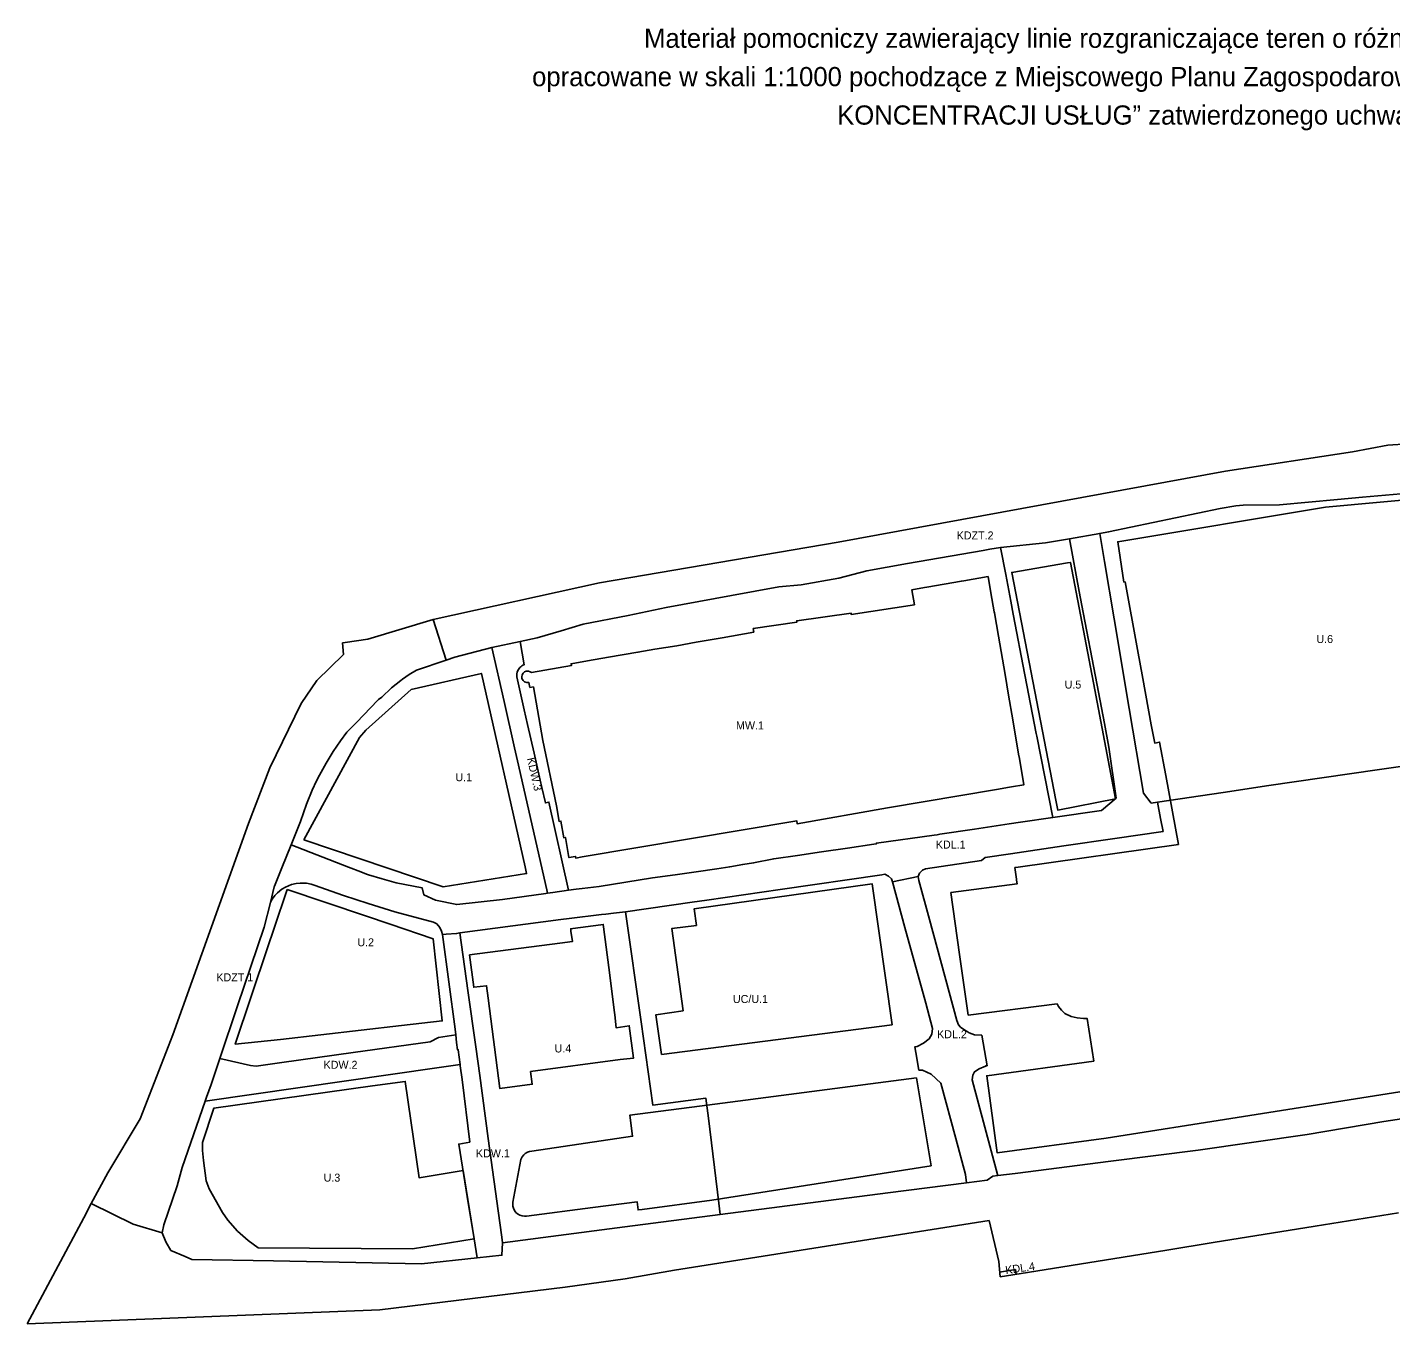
# Model space of a CAD drawing. Extents: x 7426373 to 7428079, y 5550400 to 5551210.
# Drawn here: x 7426373 to 7427225, y 5550400 to 5551210 of the extents above; entities that cross this region are included whole.
import ezdxf

# ---------------------------------------------------------------- set-up
doc = ezdxf.new("R2010")
doc.units = 0
for name, color, linetype in [('info', 7, 'Continuous'), ('linie rozgraniczające', 7, 'Continuous'), ('nieprzekraczalne linie zabudowy', 7, 'Continuous'), ('obowiazujace linie zabudowy', 7, 'Continuous'), ('przeznaczenia terenów', 7, 'Continuous')]:
    doc.layers.add(name, color=color, linetype=linetype)

msp = doc.modelspace()

# ---------------------------------------------------------------- linework, layer by layer
at = {"layer": 'linie rozgraniczające'}
for p, q in [((7427200.83, 5550944.38), (7427121.57, 5550932.18)), ((7427121.57, 5550932.18), (7426879.43, 5550887.96)), ((7426879.43, 5550887.96), (7426730.45, 5550862.43)), ((7426730.45, 5550862.43), (7426626.47, 5550839.54)), ((7426626.47, 5550839.54), (7426634.6, 5550814.16)), ((7426571.44, 5550825.22), (7426569.8, 5550824.98)), ((7426569.8, 5550824.98), (7426570.42, 5550817.78)), ((7426544.01, 5550787.1), (7426524.3, 5550746.79)), ((7426913.49, 5550675.69), (7426929.4, 5550678.9)), ((7426408.16, 5550465.79), (7426372.85, 5550399.52)), ((7426777.24, 5550432.91), (7426973.92, 5550463.96)), ((7426973.92, 5550463.96), (7426979.89, 5550438.33)), ((7426979.89, 5550438.33), (7426980.6, 5550428.75)), ((7426746.5, 5550427.54), (7426777.24, 5550432.91)), ((7426990.26, 5550433.4), (7426980.37, 5550431.84)), ((7426990.59, 5550430.37), (7426990.26, 5550433.4))]:
    msp.add_line(p, q, dxfattribs=at)
for points in [[(7427299.9, 5550956.76), (7427299.03, 5550953.57), (7427222.94, 5550948.43), (7427200.83, 5550944.38)], [(7427231.06, 5550918.04), (7427207, 5550916.03), (7427191.46, 5550914.56), (7427155.25, 5550911.14), (7427132.43, 5550911.02), (7427128, 5550910.66), (7427118.17, 5550908.95), (7427048.39, 5550894.28), (7427042.86, 5550893.33), (7427023.95, 5550890.06), (7427008.92, 5550887.47), (7426980.93, 5550884.56), (7426974.25, 5550883.46), (7426970.17, 5550882.71), (7426922.78, 5550874.54), (7426897.33, 5550869.9), (7426879.87, 5550865.38), (7426856.3, 5550861.2), (7426842.51, 5550859.92), (7426812.77, 5550854.5), (7426772.12, 5550847.06), (7426748.24, 5550842.12), (7426720.26, 5550836.75), (7426706.41, 5550832.57), (7426691.43, 5550828.11)], [(7427043.94, 5550720.28), (7427053.16, 5550727.95), (7427048.64, 5550759.91), (7427045.81, 5550774.61), (7427040.16, 5550804.03), (7427032.61, 5550844), (7427030.14, 5550857.04), (7427023.95, 5550890.06)], [(7427074.95, 5550724.79), (7427070.3, 5550731.05), (7427061.21, 5550783.95), (7427051.87, 5550839.95), (7427045.87, 5550875.92), (7427042.86, 5550893.33)], [(7426980.93, 5550884.56), (7426984.14, 5550867.7), (7426987.35, 5550851.06), (7426988.81, 5550842.84), (7426991.04, 5550831.04), (7426993.72, 5550816.94), (7427003.23, 5550768.45), (7427003.57, 5550766.7), (7427013.55, 5550715.81)], [(7426626.47, 5550839.54), (7426585.7, 5550827.19), (7426571.44, 5550825.22)], [(7426524.72, 5550662.81), (7426527.19, 5550672.58), (7426527.36, 5550673), (7426531.93, 5550684.33), (7426537.7, 5550698.68), (7426543.64, 5550713.44), (7426547.28, 5550724.24), (7426550.84, 5550733.01), (7426553.65, 5550738.79), (7426555.39, 5550742.41), (7426559.69, 5550749.76), (7426563.99, 5550757.12), (7426568.62, 5550763.72), (7426572.53, 5550769.08), (7426578.54, 5550775.3), (7426591.9, 5550789.09), (7426592.39, 5550789.67), (7426594.4, 5550791.12), (7426600.45, 5550796.8), (7426603.39, 5550799.16), (7426606.33, 5550801.51), (7426607.38, 5550802.27), (7426611.43, 5550805.25), (7426615.97, 5550807.98), (7426634.6, 5550814.16), (7426640, 5550815.95), (7426663.15, 5550822.11), (7426680.85, 5550825.86), (7426691.43, 5550828.11)], [(7426663.15, 5550822.11), (7426670.78, 5550788.36), (7426677.33, 5550759.36), (7426679.17, 5550751.18), (7426697.37, 5550670.68), (7426697.85, 5550668.55)], [(7426680.85, 5550825.86), (7426683.34, 5550811.31), (7426682.55, 5550810.97), (7426681.9, 5550810.58), (7426681.2, 5550810.05), (7426680.62, 5550809.49), (7426680.15, 5550808.92), (7426679.41, 5550807.72), (7426678.99, 5550806.65), (7426678.74, 5550805.54), (7426678.67, 5550804.29), (7426678.74, 5550803.66), (7426683.4, 5550783.18), (7426685.48, 5550773.89), (7426689.5, 5550756.06), (7426690.79, 5550750.53), (7426692.91, 5550740.96), (7426693.3, 5550739.23), (7426694.28, 5550734.61), (7426696.53, 5550724.93), (7426698.72, 5550725.49), (7426711.08, 5550670.36)], [(7426570.42, 5550817.78), (7426553.66, 5550801.56), (7426544.01, 5550787.1)], [(7427281.67, 5550755.01), (7427216.25, 5550745.55), (7427148.47, 5550735.75), (7427120.11, 5550731.52), (7427078.99, 5550725.38), (7427074.95, 5550724.79)], [(7426524.3, 5550746.79), (7426511.17, 5550712.2), (7426463.78, 5550579.96)], [(7427078.99, 5550725.38), (7427080.96, 5550715.19), (7427082.53, 5550707.01)], [(7427043.94, 5550720.28), (7427013.55, 5550715.81), (7426993.42, 5550712.93), (7426986.37, 5550711.87), (7426964.74, 5550708.62), (7426943.1, 5550705.38), (7426941.25, 5550705.12), (7426939.4, 5550704.86), (7426903.41, 5550699.82), (7426903.51, 5550699.49), (7426901.68, 5550699.23), (7426885.36, 5550696.76), (7426869.03, 5550694.3), (7426854.16, 5550692.2), (7426839.28, 5550690.09), (7426826.6, 5550687.52), (7426819.84, 5550686.5), (7426811.75, 5550685.11), (7426803.66, 5550683.71), (7426790.69, 5550681.84), (7426777.72, 5550679.97), (7426763.45, 5550678.23), (7426730.17, 5550672.78), (7426719.53, 5550671.43), (7426715.8, 5550670.99), (7426711.08, 5550670.36), (7426701.12, 5550669.03), (7426697.85, 5550668.55), (7426696.81, 5550668.4), (7426669.74, 5550664.65), (7426641.2, 5550661.4), (7426627.88, 5550664.24), (7426620.57, 5550667.61), (7426619.64, 5550671.82), (7426603.32, 5550675), (7426594.65, 5550677.53), (7426585.97, 5550680.05), (7426584.78, 5550680.51), (7426581.25, 5550681.89), (7426573.65, 5550684.85), (7426537.7, 5550698.68)], [(7427082.53, 5550707.01), (7427052.26, 5550702.77), (7427020.37, 5550698.12), (7426987.13, 5550693.16), (7426971.27, 5550690.94), (7426969.02, 5550688.97), (7426934.05, 5550683.87), (7426932.12, 5550683.05), (7426930.2, 5550681.05), (7426929.4, 5550678.9), (7426929.93, 5550676.45), (7426936.44, 5550652.18), (7426953.6, 5550588.92), (7426954.62, 5550586.38), (7426955.96, 5550584.85), (7426958.58, 5550582.95), (7426960.08, 5550582.09), (7426961.4, 5550581.35), (7426964.66, 5550579.98), (7426969.15, 5550579.78), (7426972.52, 5550560.71), (7426971.43, 5550560.58), (7426971.46, 5550560.4), (7426967.5, 5550558.84), (7426964.65, 5550556.93), (7426963.52, 5550554.77), (7426963.28, 5550551.9), (7426979.05, 5550492.76), (7426979.22, 5550492.13)], [(7426570.38, 5550667.05), (7426552.01, 5550673.64), (7426550.21, 5550674.16), (7426547.24, 5550674.73), (7426546.41, 5550674.84), (7426544.92, 5550674.91), (7426543.43, 5550674.91), (7426540.9, 5550674.69), (7426537.86, 5550673.94), (7426534.16, 5550672.34), (7426531.8, 5550671), (7426529.21, 5550668.88), (7426527.52, 5550667.11), (7426525.77, 5550664.78), (7426524.72, 5550662.81)], [(7426959.64, 5550487.59), (7426959.07, 5550492.74), (7426953.02, 5550515.22), (7426943.72, 5550549.78), (7426937.52, 5550555.5), (7426932.11, 5550558), (7426929.96, 5550558.02), (7426928.05, 5550568.96), (7426927.46, 5550572.57), (7426928.81, 5550572.74), (7426932.87, 5550574.92), (7426936.27, 5550577.63), (7426937.91, 5550580.54), (7426938.39, 5550584.1), (7426934.3, 5550599.93), (7426921.05, 5550647.07), (7426913.49, 5550675.69), (7426912.78, 5550677.58), (7426910.99, 5550679.29), (7426908.69, 5550680.35), (7426906.69, 5550680.05), (7426843.33, 5550670.89), (7426797.43, 5550664.26), (7426788.2, 5550662.92), (7426746.58, 5550656.9), (7426739.16, 5550656.05), (7426734.36, 5550655.47), (7426731.7, 5550655.17), (7426711.51, 5550652.67), (7426706.29, 5550652.03), (7426654.05, 5550645.24), (7426643.2, 5550643.74), (7426641.05, 5550643.37), (7426634.48, 5550642.9), (7426632.36, 5550642.72), (7426631.71, 5550644.74), (7426630.6, 5550647.15), (7426628.75, 5550649.41), (7426626.68, 5550650.52), (7426602.56, 5550656.94), (7426585.82, 5550662.05), (7426570.38, 5550667.05)], [(7426484.91, 5550541.11), (7426487.67, 5550549.1), (7426493.12, 5550565.25), (7426504.24, 5550598.2), (7426520.81, 5550647.3), (7426524.72, 5550662.81)], [(7426746.58, 5550656.9), (7426756.3, 5550588.21), (7426763.64, 5550536.2), (7426796.7, 5550540.55), (7426798.47, 5550527.9), (7426804.92, 5550474.95), (7426805.8, 5550467.73)], [(7426632.36, 5550642.72), (7426640.23, 5550583.58), (7426640.6, 5550580.07), (7426641.09, 5550575.27), (7426641.57, 5550570.68), (7426642.14, 5550570.77), (7426643.31, 5550561.53), (7426643.41, 5550560.74), (7426644.5, 5550552.12), (7426649.44, 5550512.93)], [(7426669.77, 5550450.17), (7426669.3, 5550453.64), (7426668.09, 5550462.55), (7426660.9, 5550515.36), (7426655.56, 5550554.61), (7426653.07, 5550572.53), (7426648.18, 5550607.78), (7426643.2, 5550643.74)], [(7426463.78, 5550579.96), (7426443.36, 5550527.61), (7426423.09, 5550493.8)], [(7426640.6, 5550580.07), (7426629.76, 5550578.4), (7426624.47, 5550575.59), (7426576.42, 5550568.92), (7426531.86, 5550562.73), (7426515.91, 5550560.51), (7426512.41, 5550560.84), (7426493.12, 5550565.25)], [(7426643.31, 5550561.53), (7426630.27, 5550559.66), (7426484.06, 5550538.65)], [(7426462.57, 5550445.22), (7426459.41, 5550450.72), (7426457.17, 5550456.35), (7426458.12, 5550461.3), (7426466.43, 5550485.7), (7426469.73, 5550497.17), (7426484.06, 5550538.65), (7426484.91, 5550541.11)], [(7426669.77, 5550450.17), (7426699.86, 5550454.06), (7426746.19, 5550460.04), (7426805.8, 5550467.73), (7426910.55, 5550481.26), (7426959.64, 5550487.59), (7426966.2, 5550488.44), (7426972.53, 5550489.26), (7426976.08, 5550491.73), (7426979.22, 5550492.13), (7426990.13, 5550493.5), (7427049.79, 5550501.06), (7427104.38, 5550507.97), (7427172.42, 5550517.71), (7427220.33, 5550525.84), (7427254.95, 5550531.02)], [(7426649.44, 5550512.93), (7426642.42, 5550511.79), (7426648.6, 5550473.89), (7426652.07, 5550452.58), (7426652.73, 5550448.53), (7426654, 5550440.74)], [(7426423.09, 5550493.8), (7426412.87, 5550474.63), (7426408.16, 5550465.79)], [(7426457.17, 5550456.35), (7426439.06, 5550461.64), (7426412.87, 5550474.63)], [(7426980.6, 5550428.75), (7426984.66, 5550429.41), (7426997.74, 5550431.53), (7427084.76, 5550445.54), (7427113.69, 5550450.21), (7427177.53, 5550460.5), (7427229.52, 5550468.88)], [(7426462.57, 5550445.22), (7426471.47, 5550441.49), (7426475.58, 5550439.76), (7426526.67, 5550438.74), (7426619.15, 5550436.96), (7426654, 5550440.74), (7426669.39, 5550442.28), (7426669.77, 5550450.17)], [(7426372.85, 5550399.52), (7426482.98, 5550403.88), (7426593.12, 5550408.24), (7426651.03, 5550415.3), (7426708.95, 5550422.37), (7426746.5, 5550427.54)]]:
    msp.add_lwpolyline(points, dxfattribs=at)
at = {"layer": 'nieprzekraczalne linie zabudowy'}
for p, q in [((7426694.94, 5550764.02), (7426694.94, 5550764.02)), ((7426530.97, 5550577.15), (7426606.59, 5550585.87))]:
    msp.add_line(p, q, dxfattribs=at)
for points in [[(7427408.31, 5550895.03), (7427406.05, 5550895.78), (7427347.6, 5550914.84), (7427315.95, 5550921.81), (7427184.04, 5550909.87), (7427054.18, 5550888.2), (7427058.04, 5550862.98), (7427058.77, 5550863.09), (7427066.5, 5550820.89)], [(7426987.97, 5550868.97), (7426987.97, 5550868.97), (7427015.49, 5550726.69), (7427016.7, 5550720.54), (7427052.76, 5550727.61), (7427039.91, 5550795.68), (7427024.56, 5550875.24), (7427022.74, 5550874.93), (7426987.97, 5550868.97)], [(7426927.21, 5550848.81), (7426887.65, 5550842.69), (7426887.61, 5550843.46), (7426853.56, 5550838.75), (7426853.69, 5550837.92), (7426826.46, 5550833.95), (7426826.86, 5550831.58)], [(7426683.89, 5550684.97), (7426656.55, 5550805.94), (7426612.68, 5550795.74), (7426584.31, 5550770.39), (7426580.37, 5550765.79), (7426545.71, 5550701.93)], [(7426694.94, 5550764.02), (7426703.47, 5550723.24), (7426705.09, 5550713.44), (7426706.24, 5550713.64), (7426708.03, 5550703.23), (7426709.08, 5550703.41), (7426711.25, 5550690.78), (7426715.39, 5550691.49), (7426715.55, 5550690.53), (7426719.6, 5550691.23)], [(7427084.17, 5550742.1), (7427092.19, 5550698.96)], [(7426719.6, 5550691.23), (7426853.7, 5550713.68), (7426853.84, 5550711.91), (7426910.3, 5550721.97), (7426978.42, 5550733.32)], [(7426545.71, 5550701.93), (7426632.77, 5550672.51), (7426684.82, 5550680.83), (7426683.89, 5550684.97)], [(7427092.19, 5550698.96), (7426992.04, 5550684.88), (7426989.87, 5550684.57)], [(7426989.87, 5550684.57), (7426990.86, 5550677.31), (7426990.87, 5550676.7), (7426991.27, 5550674.33), (7426949.91, 5550668.98), (7426955.34, 5550630.15), (7426957.17, 5550617.07), (7426960.63, 5550592.33)], [(7427046.83, 5550515.5), (7427456.13, 5550580.05), (7427468.63, 5550624.1)], [(7426960.63, 5550592.33), (7427016.25, 5550599.49)], [(7427016.25, 5550599.49), (7427017.05, 5550597.81), (7427018.92, 5550595.38), (7427021.11, 5550593.35), (7427024.97, 5550591.54), (7427028.9, 5550590.68), (7427032.73, 5550590.2), (7427034.96, 5550590.32), (7427039.19, 5550563.67)], [(7427039.19, 5550563.67), (7426972.3, 5550554.51), (7426978.92, 5550506.25), (7427046.83, 5550515.5)], [(7426517.15, 5550446.9), (7426613.55, 5550446.31), (7426652.07, 5550452.58), (7426645.12, 5550495.22), (7426617.67, 5550490.74), (7426608.97, 5550550.97), (7426588.44, 5550548.09), (7426489.35, 5550534.19), (7426482.29, 5550512.71)], [(7426800.47, 5550476.65), (7426937.48, 5550498.26), (7426928.41, 5550553.09)]]:
    msp.add_lwpolyline(points, dxfattribs=at)
at = {"layer": 'obowiazujace linie zabudowy'}
for p, q in [((7427084.17, 5550742.09), (7427084.17, 5550742.09)), ((7426769.1, 5550567.67), (7426913.22, 5550586.23))]:
    msp.add_line(p, q, dxfattribs=at)
for points in [[(7426978.42, 5550733.32), (7426986.52, 5550734.72), (7426987.67, 5550734.92), (7426995.55, 5550736.28), (7426992.49, 5550754.06), (7426992.37, 5550754.17), (7426988.61, 5550776.98), (7426985.99, 5550792.24), (7426983.76, 5550805.11), (7426979.62, 5550829.07), (7426977.08, 5550843.77), (7426976.98, 5550844.34), (7426974.91, 5550856.31), (7426973.16, 5550866.42), (7426958, 5550863.8), (7426956.52, 5550863.55), (7426934.97, 5550859.83), (7426933.45, 5550859.57), (7426925.58, 5550858.22), (7426927.21, 5550848.81)], [(7426826.86, 5550831.58), (7426806.94, 5550828.15), (7426790.79, 5550825.37), (7426778.6, 5550823.18), (7426764.96, 5550820.99), (7426754.4, 5550819.12), (7426736.08, 5550815.98), (7426722.95, 5550813.71), (7426712.62, 5550811.92), (7426712.82, 5550810.77), (7426687.82, 5550806.44), (7426687.03, 5550806.87), (7426686.09, 5550807.28), (7426685.59, 5550807.37), (7426684.49, 5550807.25), (7426683.5, 5550806.89), (7426682.59, 5550806.06), (7426682.1, 5550805.06), (7426681.76, 5550803.81), (7426681.92, 5550802.66), (7426682.6, 5550801.42), (7426683.54, 5550800.57), (7426684.97, 5550800.2), (7426686.26, 5550800.12), (7426686.84, 5550797.17), (7426689.04, 5550797.43), (7426694.94, 5550764.02)], [(7427066.5, 5550820.89), (7427069.81, 5550802.73), (7427075.13, 5550773.73), (7427077.24, 5550762.35), (7427080.3, 5550762.95), (7427084.17, 5550742.12)], [(7426913.22, 5550586.23), (7426900.66, 5550674.42), (7426789.53, 5550658.81), (7426790.96, 5550648.4)], [(7426535.27, 5550670.86), (7426527.12, 5550646.62), (7426523.04, 5550634.47), (7426502.76, 5550574.13), (7426530.97, 5550577.15)], [(7426606.59, 5550585.87), (7426632.13, 5550588.74), (7426626.36, 5550640.08), (7426599.5, 5550649.15), (7426584.18, 5550654.33), (7426535.27, 5550670.86)], [(7426790.96, 5550648.4), (7426775.46, 5550646.4), (7426782.74, 5550594.99)], [(7426782.74, 5550594.97), (7426765.6, 5550592.56), (7426769.1, 5550567.67)], [(7426928.41, 5550553.09), (7426792.9, 5550535.56), (7426749.39, 5550529.93), (7426751.08, 5550516.72), (7426688.18, 5550507.36), (7426686.66, 5550507.13), (7426685.31, 5550506.65), (7426683.99, 5550505.86), (7426683.03, 5550505.01), (7426682.05, 5550503.73), (7426681.27, 5550502.22), (7426676.24, 5550475.42), (7426676.24, 5550472.98), (7426676.54, 5550471.78), (7426677.22, 5550470.33), (7426678.12, 5550469.12), (7426679.2, 5550468.16), (7426680.5, 5550467.4), (7426681.98, 5550466.89), (7426683.41, 5550466.71), (7426684.76, 5550466.79), (7426726.21, 5550472.15), (7426753.84, 5550475.72), (7426754.49, 5550470.64), (7426756.96, 5550470.96), (7426800.47, 5550476.65)], [(7426482.29, 5550512.71), (7426482.4, 5550507.8), (7426482.99, 5550501.58), (7426484.69, 5550488.77), (7426486.46, 5550483.8)], [(7426486.46, 5550483.8), (7426494.92, 5550468.97), (7426498.23, 5550464.16), (7426504.2, 5550457.45), (7426510.84, 5550451.5), (7426517.15, 5550446.9)]]:
    msp.add_lwpolyline(points, dxfattribs=at)
msp.add_lwpolyline([(7426649.11, 5550630.05), (7426649.11, 5550630.04), (7426651.75, 5550609.74), (7426659.78, 5550610.77), (7426660.79, 5550602.94), (7426668.04, 5550546.52), (7426688.35, 5550549.14), (7426687.32, 5550557.13), (7426687.32, 5550557.13), (7426743.34, 5550564.56), (7426751.58, 5550565.41), (7426748.97, 5550585.74), (7426740.76, 5550584.48), (7426739.98, 5550592.54), (7426739.79, 5550593.98), (7426736.13, 5550622.11), (7426732.85, 5550647.54), (7426732.66, 5550649), (7426731.2, 5550648.81), (7426713.8, 5550646.55), (7426712.36, 5550646.36), (7426712.55, 5550644.92), (7426713.4, 5550638.36), (7426705.56, 5550637.37), (7426705.53, 5550637.37)], close=True, dxfattribs=at)

# ---------------------------------------------------------------- texts
at = {"layer": 'info'}
for s, p in [('Materiał pomocniczy zawierający linie rozgraniczające teren o różnym przeznaczeniu i różnych warunkach zagospodarowania terenu, ', (7426758.2, 5551196.82)), ('opracowane w skali 1:1000 pochodzące z Miejscowego Planu Zagospodarowania Przestrzennego obszaru „GEN. BORA-KOMOROWSKIEGO - REJON ', (7426688.24, 5551172.82)), ('KONCENTRACJI USŁUG” zatwierdzonego uchwałą RMK Nr CXI/2954/18 z dnia 26 września 2018 r.', (7426878.83, 5551148.82))]:
    msp.add_text(s, height=12, dxfattribs=at).set_placement(p)
at = {"layer": 'przeznaczenia terenów'}
for s, p in [('KDZT.2', (7426953.51, 5550889.61)), ('U.6', (7427178.27, 5550824.88)), ('U.5', (7427020.97, 5550796.43)), ('MW.1', (7426815.66, 5550770.89)), ('U.1', (7426640.36, 5550738.53)), ('KDL.1', (7426940.49, 5550696.44)), ('U.2', (7426579.09, 5550635.37)), ('KDZT.1', (7426491, 5550613.5)), ('UC/U.1', (7426813.73, 5550599.93)), ('KDL.2', (7426941.29, 5550577.93)), ('U.4', (7426702.3, 5550569.05)), ('KDW.2', (7426557.98, 5550558.82)), ('KDW.1', (7426653.17, 5550503.49)), ('U.3', (7426558, 5550488.32))]:
    msp.add_text(s, height=5, dxfattribs=at).set_placement(p)
for s, rotation, p in [('KDW.3', 282.81487, (7426684.98, 5550752.75)), ('KDL.4', 8.23654, (7426984.3, 5550430.49))]:
    msp.add_text(s, height=5, rotation=rotation, dxfattribs=at).set_placement(p)

doc.saveas('drawing.dxf')
